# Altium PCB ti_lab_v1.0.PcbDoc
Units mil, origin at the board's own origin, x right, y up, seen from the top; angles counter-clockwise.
Board outline 7140.03 x 8380.03 mil, 2 copper layers (Top Layer, Bottom Layer); 143 components, 45 nets, 464 pads, 229 vias.
Unrouted connection lines stored in the file: 7.
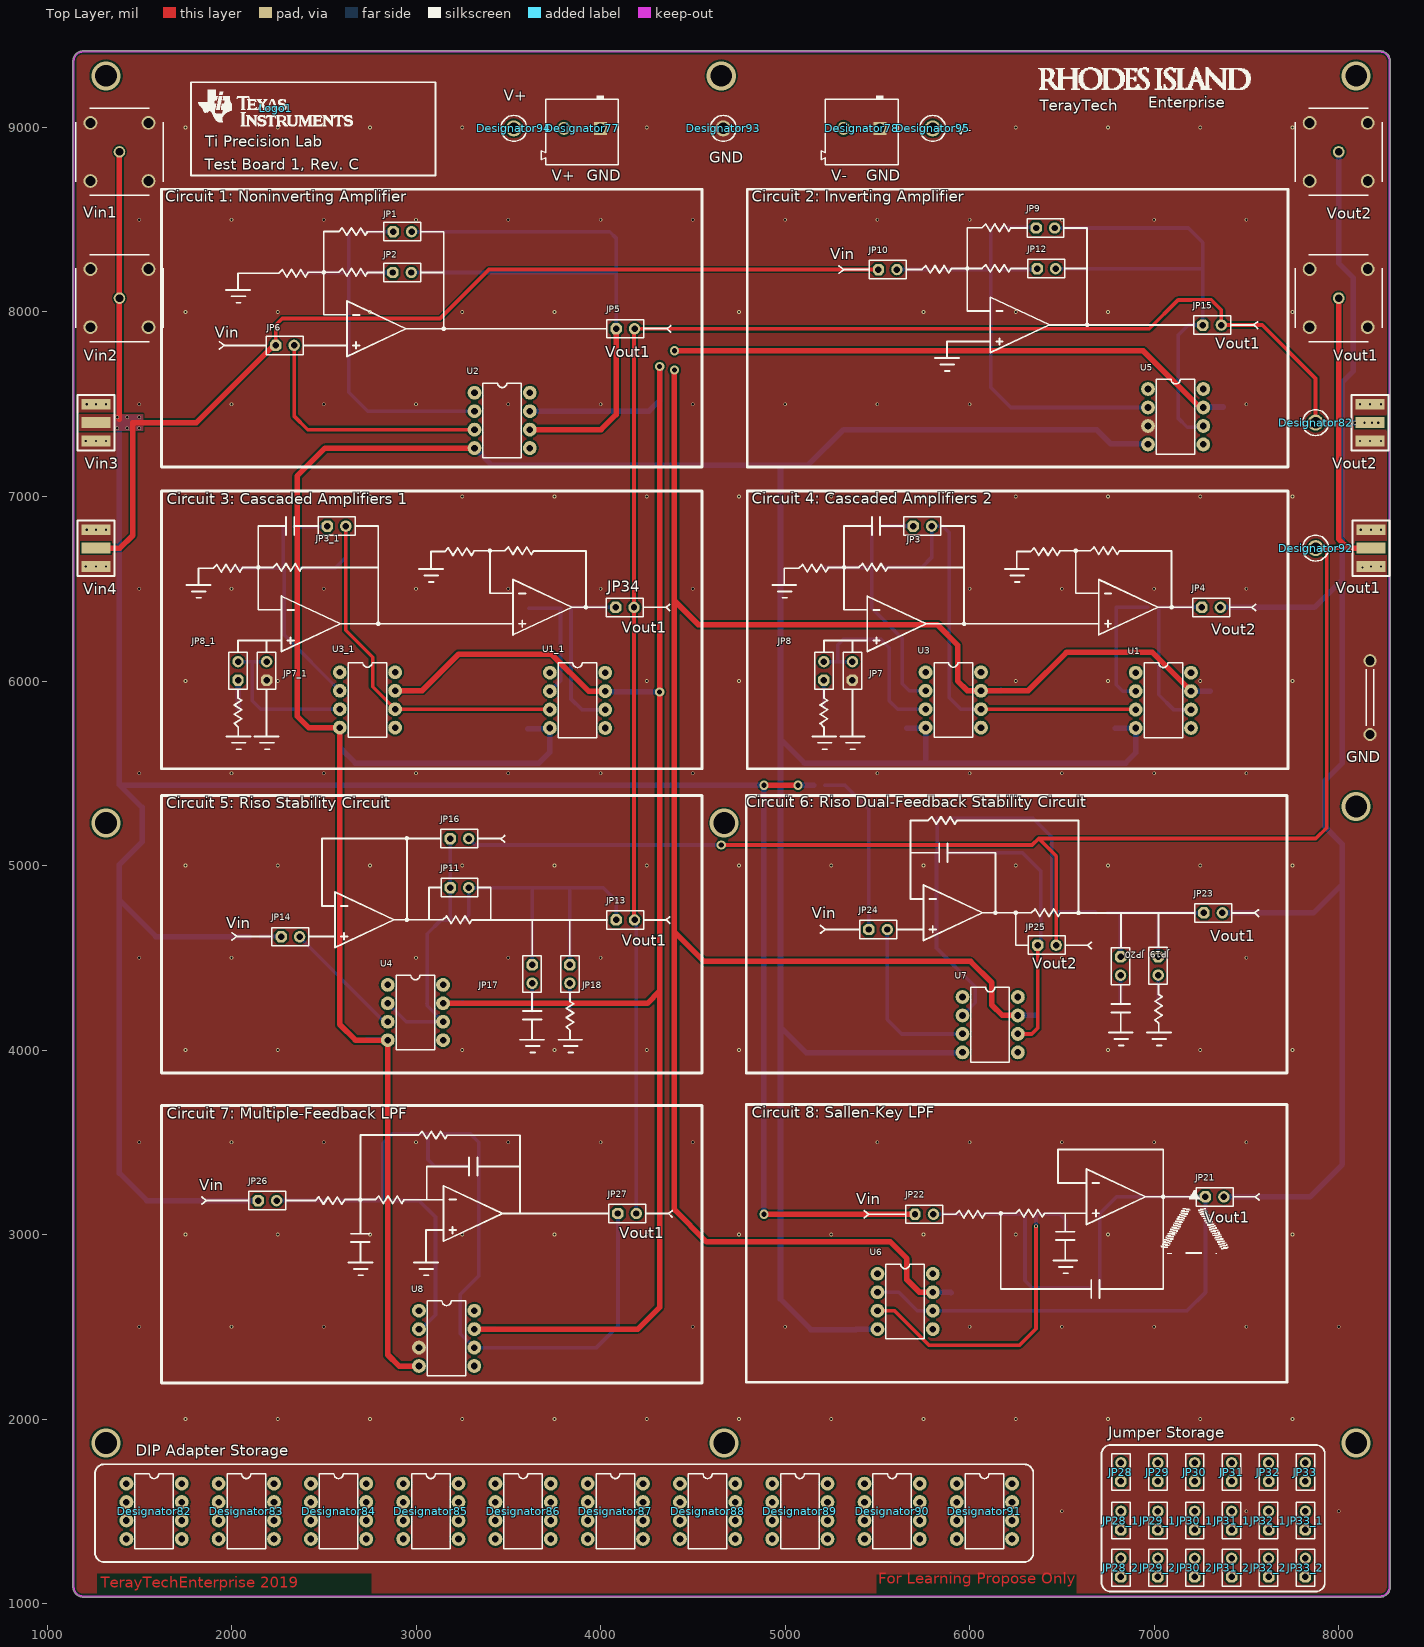
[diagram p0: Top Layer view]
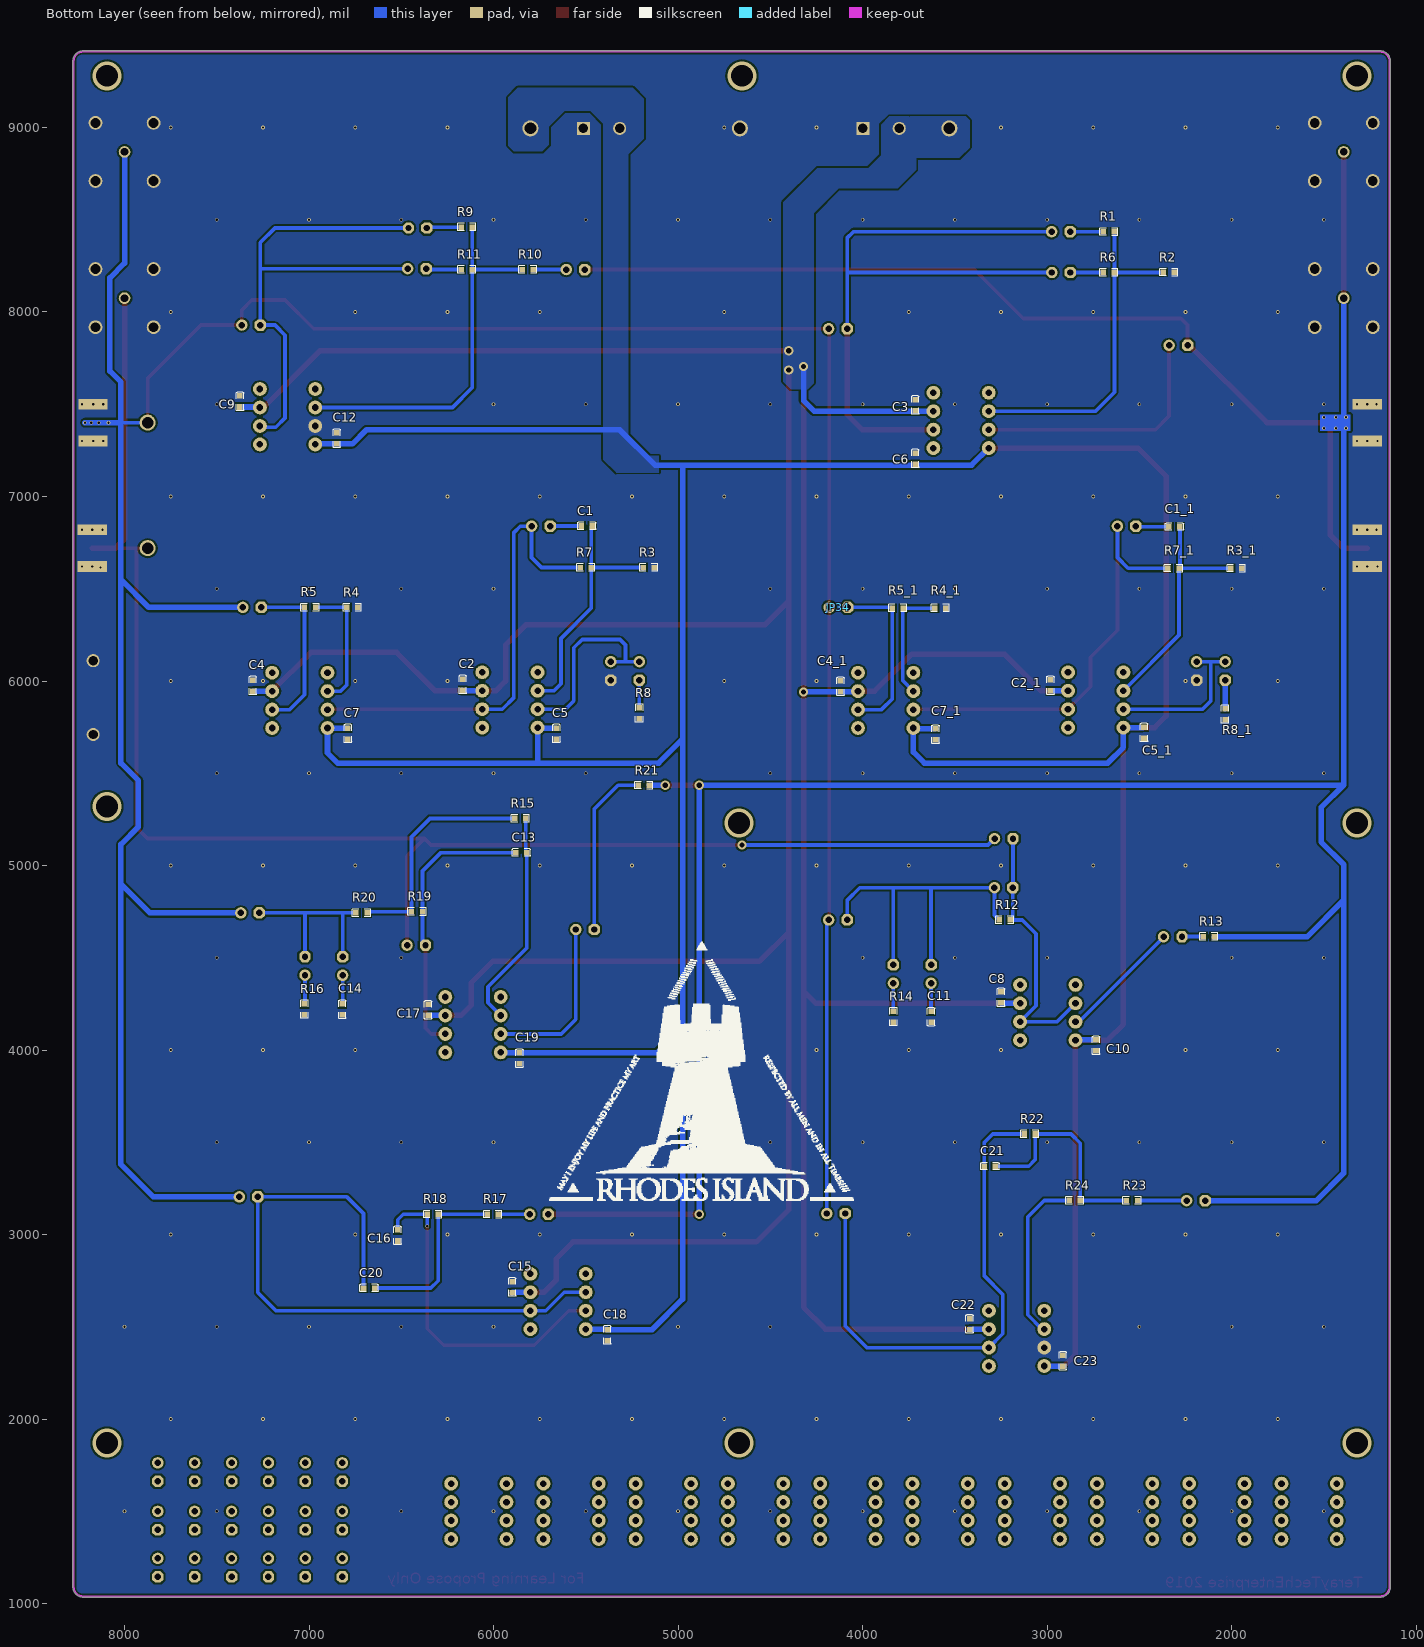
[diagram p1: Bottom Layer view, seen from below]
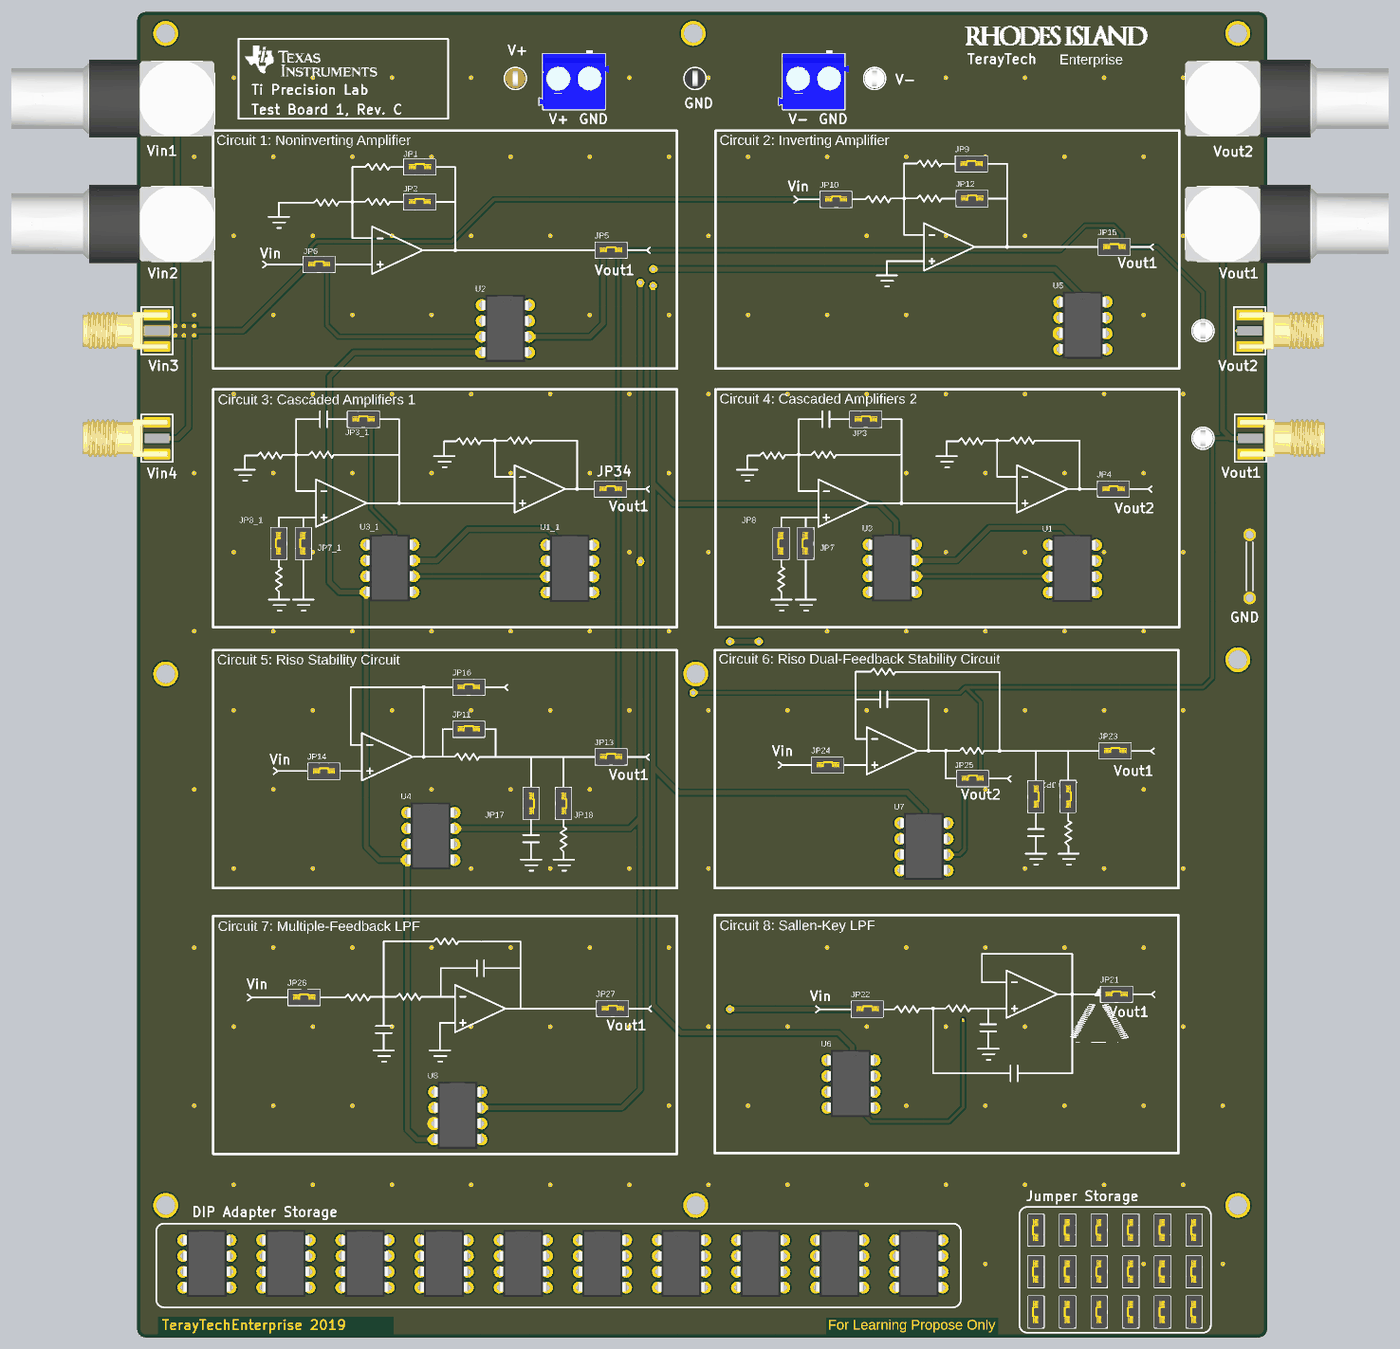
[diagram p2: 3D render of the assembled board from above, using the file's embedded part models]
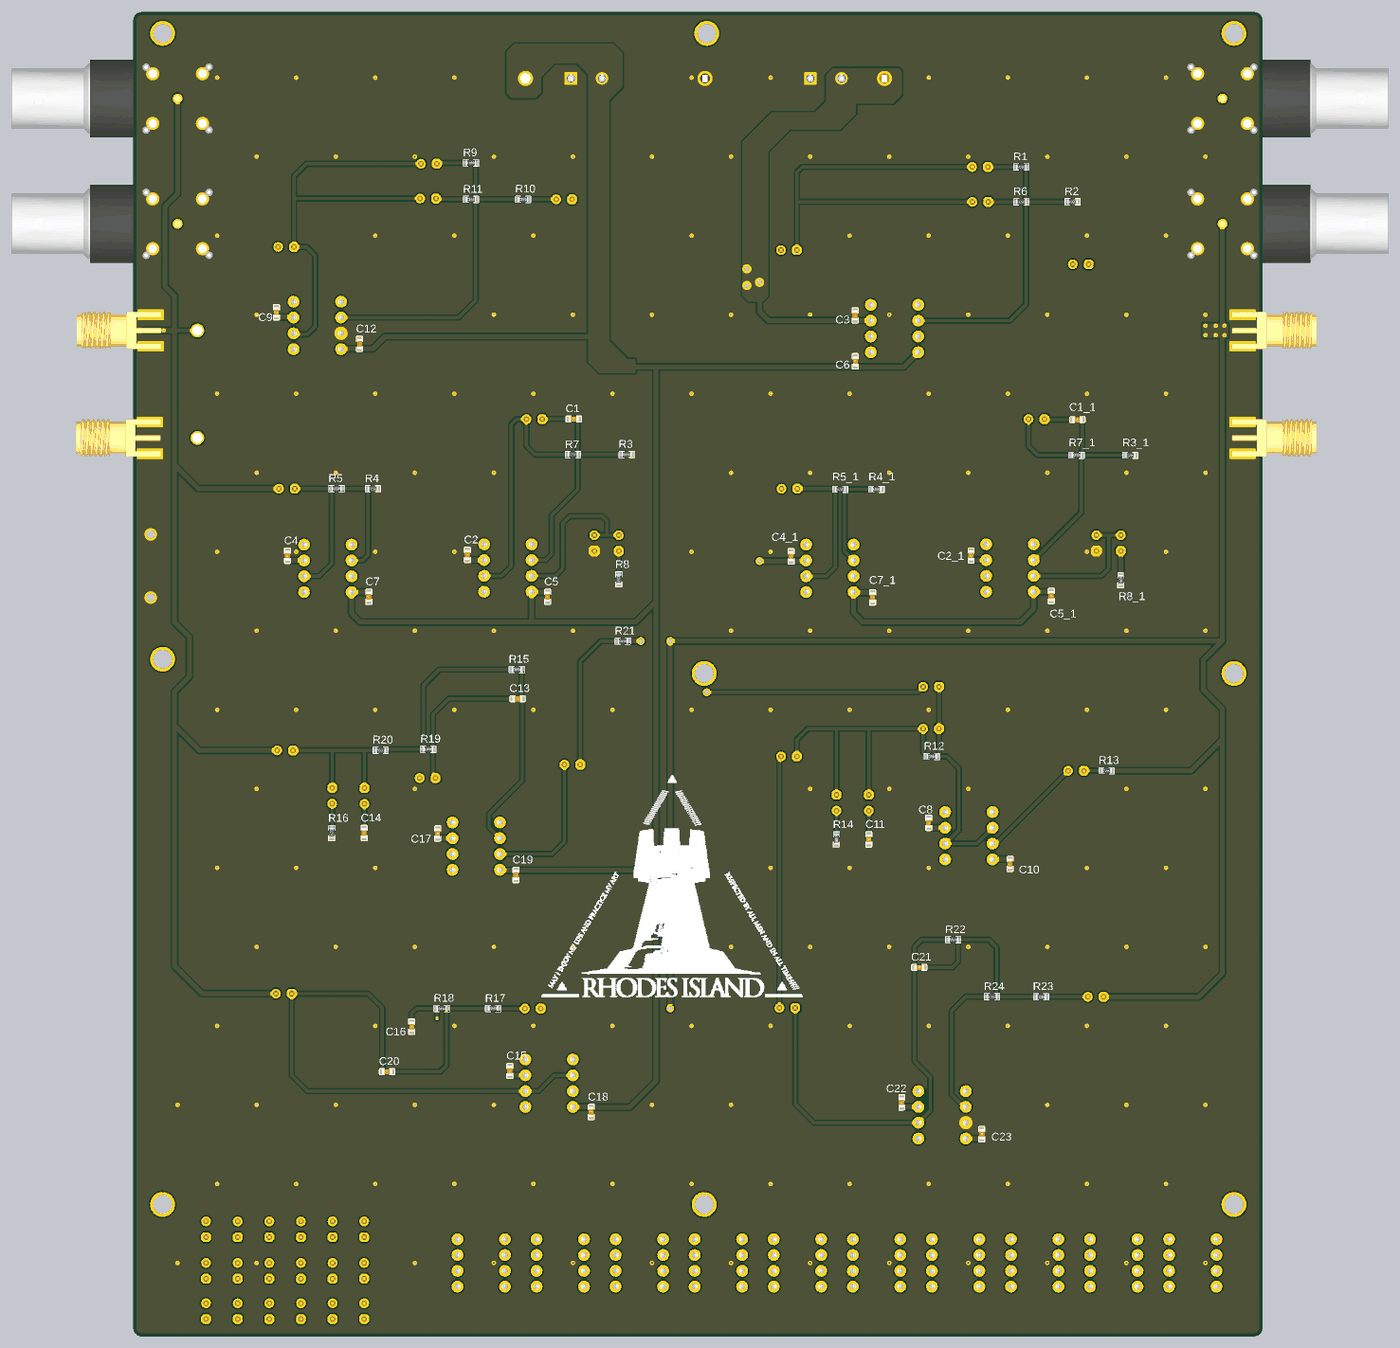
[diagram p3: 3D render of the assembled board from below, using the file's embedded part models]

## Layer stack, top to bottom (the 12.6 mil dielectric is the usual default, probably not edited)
Top Solder: solder mask 0.4, Solder Resist, Dk 3.5
Top Layer: signal copper 1.4
Dielectric 1: dielectric 12.6, FR-4, Dk 4.8
Bottom Layer: signal copper 1.4
Bottom Solder: solder mask 0.4, Solder Resist, Dk 3.5

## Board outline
1139.98,1090 ccw(c1195,1090) 1195,1034.98 8225,1034.98 ccw(c8225,1090) 8280.01,1090 8280.01,9360 ccw(c8225,9360) 8225,9415.01 1195,9415.01 ccw(c1195,9360) 1139.98,9360

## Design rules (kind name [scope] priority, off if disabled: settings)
Clearance [All] p1: gap=10 ignorepadtopadclearanceinfootprint=FALSE except(0: Arc-Hole Track-Hole SMDPad-Hole THPad-Hole Via-Hole Fill-Hole Poly-Hole Region-Hole Text-Hole)
PolygonConnect [All] p1: connectstyle=Direct reliefconductorwidth=10 reliefentries=4 polygonreliefangle="90 Angle" airgapwidth=10
RoutingVias [All] p1: holewidth=28 width=50 viastyle="Through Hole" minholewidth=28 minwidth=50 maxholewidth=28 maxwidth=50
SolderMaskExpansion [All] p1: expansion=4
Width [All] p1: maxlimit=30 minlimit=10 preferedwidth=20 minimp=50.000000 maximp=50.000000 favimp=50.000000
30 further rules are at their usual default settings.

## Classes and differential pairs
component class ti_lab: C1 C2 C3 C4 C5 C6 C7 C8 C9 C10 C11 C12 C13 C14 C15 C16 C17 C18 C19 C20 C21 C22 C23 JP1 JP2 JP3 JP4 JP5 JP6 JP7 JP8 JP9 JP10 JP11 JP12 JP13 JP14 JP15 JP16 JP17 JP18 JP19 JP20 JP21 JP22 JP23 JP24 JP25 JP26 JP27 Logo1 R1 R2 R3 R4 R5 R6 R7 R8 R9 R10 R11 R12 R13 R14 R15 R16 R17 R18 R19 R20 R21 R22 R23 R24 U1 U2 U3 U4 U5 U6 U7 U8 Vin4 Vout1 Vout2

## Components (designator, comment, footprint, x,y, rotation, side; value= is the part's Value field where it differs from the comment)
C1 "0.01uF" 0603_C 5495,6840 r0 bottom value=104
C1_1 "0.01uF" 0603_C 2310,6836 r0 bottom value=104
C2 "1uF" 0603_C 6167.28,5980 r90 bottom value=104
C2_1 "1uF" 0603_C 2982.28,5976 r90 bottom value=104
C3 "1uF" 0603_C 3715,7495 r90 bottom value=104
C4 "1uF" 0603_C 7305,5975 r90 bottom value=104
C4_1 "1uF" 0603_C 4120,5971 r90 bottom value=104
C5 "1uF" 0603_C 5660,5715 r90 bottom value=104
C5_1 "1uF" 0603_C 2475,5720 r90 bottom value=104
C6 "1uF" 0603_C 3715,7205 r270 bottom value=104
C7 "1uF" 0603_C 6790,5715 r90 bottom value=104
C7_1 "1uF" 0603_C 3605,5711 r90 bottom value=104
C8 "1uF" 0603_C 3250,4285 r90 bottom value=104
C9 "1uF" 0603_C 7375,7515 r90 bottom value=104
C10 "1uF" 0603_C 2735,4025 r90 bottom value=104
C11 "1uF" 0603_C 3629,4180 r90 bottom value=104
C12 "1uF" 0603_C 6850,7315 r270 bottom value=104
C13 "1uF" 0603_C 5850,5070 r0 bottom value=104
C14 "1uF" 0603_C 6820,4220 r90 bottom value=104
C15 "1uF" 0603_C 5899,2715 r90 bottom value=104
C16 "1uF" 0603_C 6520,2995 r270 bottom value=104
C17 "1uF" 0603_C 6355,4217.28 r90 bottom value=104
C18 "1uF" 0603_C 5384,2455 r90 bottom value=104
C19 "1uF" 0603_C 5860,3955 r90 bottom value=104
C20 "0.01uF" 0603_C 6675,2710 r0 bottom value=104
C21 "10nF" 0603_C 3310,3370 r0 bottom value=104
C22 "1uF" 0603_C 3420,2515 r90 bottom value=104
C23 "1uF" 0603_C 2915,2315 r270 bottom value=104
Designator77 "Comment" Wurth_691101710002 3900,8995 r180 top
Designator78 "Comment" Wurth_691101710002 5415,8995 r180 top
Designator82 "Comment" Keystone5007 7875,7400 r270 top
Designator82 "Comment" DIP-8 1583.54,1522.72 r270 top
Designator83 "Comment" DIP-8 2083.54,1522.72 r270 top
Designator84 "Comment" DIP-8 2583.54,1522.72 r270 top
Designator85 "Comment" DIP-8 3083.54,1522.72 r270 top
Designator86 "Comment" DIP-8 3583.54,1522.72 r270 top
Designator87 "Comment" DIP-8 4083.54,1522.72 r270 top
Designator88 "Comment" DIP-8 4583.54,1522.72 r270 top
Designator89 "Comment" DIP-8 5083.54,1522.72 r270 top
Designator90 "Comment" DIP-8 5583.54,1522.72 r270 top
Designator91 "Comment" DIP-8 6083.54,1522.72 r270 top
Designator92 "Comment" Keystone5007 7875,6720 r270 top
Designator93 "Comment" Keystone5006 4665,8995 r270 top
Designator94 "Comment" Keystone5005 3530,8995 r270 top
Designator95 "Comment" Keystone5007 5800,8995 r270 top
GND "Comment" Harwin_D3082-05 8170,5910 r90 top
JP1 "jumper" jumper#1 2875.51,8435 r0 top
JP2 "jumper" jumper#1 2874,8214 r0 top
JP3 "jumper" jumper#1 5694,6839 r0 top
JP3_1 "jumper" jumper#1 2519,6839 r0 top
JP4 "jumper" jumper#1 7259,6399 r0 top
JP5 "jumper" jumper#1 4084,7909 r0 top
JP6 "jumper" jumper#1 2239,7819 r0 top
JP7 "jumper" jumper#1 5365,6005 r90 top
JP7_1 "jumper" jumper#1 2190,6005 r90 top
JP8 "jumper" jumper#1 5210,6005 r90 top
JP8_1 "jumper" jumper#1 2035,6005 r90 top
JP9 "jumper" jumper#1 6361,8455 r0 top
JP10 "jumper" jumper#1 5506,8230 r0 top
JP11 "jumper" jumper#1 3185.46,4880 r0 top
JP12 "jumper" jumper#1 6366,8235 r0 top
JP13 "jumper" jumper#1 4084,4705 r0 top
JP14 "jumper" jumper#1 2269,4614 r0 top
JP15 "jumper" jumper#1 7264,7929 r0 top
JP16 "jumper" jumper#1 3185,5146 r0 top
JP17 "jumper" jumper#1 3629,4462 r270 top
JP18 "jumper" jumper#1 3833.12,4462 r270 top
JP19 "jumper" jumper#1 6818,4505.12 r270 top
JP20 "jumper" jumper#1 7022.12,4506.12 r270 top
JP21 "jumper" jumper#1 7278,3204 r0 top
JP22 "jumper" jumper#1 5704,3110 r0 top
JP23 "jumper" jumper#1 7270,4743.24 r0 top
JP24 "jumper" jumper#1 5454,4653.12 r0 top
JP25 "jumper" jumper#1 6369,4568.12 r0 top
JP26 "jumper" jumper#1 2144,3184 r0 top
JP27 "jumper" jumper#1 4094,3114 r0 top
JP28 "jumper" jumper#1 6820,1663 r90 top (schematic designator JP21)
JP28_1 "jumper" jumper#1 6820,1400 r90 top (schematic designator JP21)
JP28_2 "jumper" jumper#1 6820,1145 r90 top (schematic designator JP21)
JP29 "jumper" jumper#1 7020,1663 r90 top (schematic designator JP21)
JP29_1 "jumper" jumper#1 7020,1400 r90 top (schematic designator JP21)
JP29_2 "jumper" jumper#1 7020,1145 r90 top (schematic designator JP21)
JP30 "jumper" jumper#1 7220,1663 r90 top (schematic designator JP21)
JP30_1 "jumper" jumper#1 7220,1400 r90 top (schematic designator JP21)
JP30_2 "jumper" jumper#1 7220,1145 r90 top (schematic designator JP21)
JP31 "jumper" jumper#1 7420,1663 r90 top (schematic designator JP21)
JP31_1 "jumper" jumper#1 7420,1400 r90 top (schematic designator JP21)
JP31_2 "jumper" jumper#1 7420,1145 r90 top (schematic designator JP21)
JP32 "jumper" jumper#1 7620,1663 r90 top (schematic designator JP21)
JP32_1 "jumper" jumper#1 7620,1400 r90 top (schematic designator JP21)
JP32_2 "jumper" jumper#1 7620,1145 r90 top (schematic designator JP21)
JP33 "jumper" jumper#1 7820,1663 r90 top (schematic designator JP21)
JP33_1 "jumper" jumper#1 7820,1400 r90 top (schematic designator JP21)
JP33_2 "jumper" jumper#1 7820,1145 r90 top (schematic designator JP21)
JP34 "jumper" jumper#2 4081.05,6399 r0 bottom (schematic designator JP4)
Logo1 "Texas Instruments" TI_Stacked_Overlay_Small 2239,9105 r0 top
R1 "10K" 0603_R 2665,8435 r0 bottom value=1K
R2 "1K" 0603_R 2340,8215 r0 bottom
R3 "1K" 0603_R 5160,6615 r0 bottom
R3_1 "1K" 0603_R 1975,6611 r0 bottom
R4 "1K" 0603_R 6765,6399 r0 bottom
R4_1 "1K" 0603_R 3580,6395 r0 bottom
R5 "20K" 0603_R 6995,6399 r0 bottom value=1K
R5_1 "20K" 0603_R 3810,6395 r0 bottom value=1K
R6 "100K" 0603_R 2665,8214 r0 bottom value=1K
R7 "100K" 0603_R 5500,6615 r0 bottom value=1K
R7_1 "100K" 0603_R 2315,6611 r0 bottom value=1K
R8 "5K" 0603_R 5210,5825 r90 bottom value=1K
R8_1 "5K" 0603_R 2035,5820 r90 bottom value=1K
R9 "10K" 0603_R 6145,8460 r0 bottom value=1K
R10 "1K" 0603_R 5815,8230 r0 bottom
R11 "100K" 0603_R 6145,8230 r0 bottom value=1K
R12 "100" 0603_R 3230,4705 r0 bottom value=1K
R13 "100" 0603_R 2125,4615 r0 bottom value=1K
R14 "100" 0603_R 3833.12,4180 r90 bottom value=1K
R15 "4.87K" 0603_R 5855,5255 r0 bottom value=1K
R16 "100" 0603_R 7025,4220 r90 bottom value=1K
R17 "4.87K" 0603_R 6005,3110 r0 bottom value=1K
R18 "14.7K" 0603_R 6330,3110 r0 bottom value=1K
R19 "100" 0603_R 6415,4750 r0 bottom value=1K
R20 "4.99" 0603_R 6715.8,4743.24 r180 bottom value=1K
R21 "100" 0603_R 5185,5435 r0 bottom value=1K
R22 "11.3K" 0603_R 3095,3545 r0 bottom value=1K
R23 "11.3K" 0603_R 2540,3184 r0 bottom value=1K
R24 "5.76K" 0603_R 2850,3185 r0 bottom value=1K
U1 "TI-OPA-8_1" DIP-8 7053.54,5917.72 r270 top
U1_1 "TI-OPA-8_1" DIP-8 3878.54,5917.72 r270 top
U2 "TI-OPA-8_1" DIP-8 3470,7435 r270 top
U3 "TI-OPA-8_1" DIP-8 5915,5920 r270 top
U3_1 "TI-OPA-8_1" DIP-8 2740,5920 r270 top
U4 "TI-OPA-8_1" DIP-8 3000,4226 r270 top
U5 "TI-OPA-8_1" DIP-8 7120,7455 r270 top
U6 "TI-OPA-8_1" DIP-8 5654,2660 r270 top
U7 "TI-OPA-8_1" DIP-8 6115,4160 r270 top
U8 "TI-OPA-8_1" DIP-8 3169,2460 r270 top
Vin1 "Comment" BNC-8X8 1392.52,8867.48 r90 top
Vin2 "Comment" BNC-8X8 1392.52,8075 r90 top
Vin3 "SMA-KHD" SMA-2 1265,7400 r270 top (schematic designator IN1)
Vin4 "SMA-KHD" SMA-2 1265,6720 r270 top
Vout1 "Comment" BNC-8X8 8000,8075 r270 top
Vout1 "SMA-KHD" SMA-2 8175,6720 r90 top (schematic designator OUT1)
Vout2 "Comment" BNC-8X8 8000,8867.48 r270 top
Vout2 "SMA-KHD" SMA-2 8170,7400 r90 top (schematic designator OUT2)

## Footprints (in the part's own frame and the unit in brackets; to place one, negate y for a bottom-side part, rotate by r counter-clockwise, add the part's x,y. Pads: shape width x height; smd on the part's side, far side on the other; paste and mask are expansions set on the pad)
0603_C [mil] "Capacitor"
  rect 30x30 smd: 1(-30,0) 2(30,0)
  silkscreen extent -50,-20 50,20, body extent -51,-18 52,21, height 35
0603_R [mil]
  rect 30x30 smd: 1(-30,0) 2(30,0)
  silkscreen extent -49,-20 49,21, body extent -32,-16 31,16, height 18
BNC-8X8 [mm]
  round 1.6 hole 1.05: 1(0,0)
  round 1.9 hole 1.35: MH(-4,-4) MH(-4,4) MH(4,-4) MH(4,4)
  silkscreen extent -6,-6 6,6, body extent -6.25,-6 6.25,26.6, height 15.25
DIP-8 [mil]
  round 75 hole 36: 1(-127.28,-153.54) 2(-27.28,-153.54) 3(72.72,-153.54) 4(172.72,-153.54) 5(172.72,146.46) 6(72.72,146.46) 7(-27.28,146.46) 8(-127.28,146.46)
  silkscreen extent -180,-108 225,101, body extent -193,-158 233,148, height 177
Harwin_D3082-05 [mm] "Shorting Plug, 10.16mm spacing, TH"
  round 1.8 hole 1.3: 1(-5.08,0) 2(5.08,0)
  silkscreen extent -3.9,-0.53 3.9,0.53, body extent -5.6,-0.52 5.61,0.52, height 6.63
jumper#1 [mil]
  round 1 on Mech3: 0(51,1)
  oct 62x62 hole 35: 1(0,0)
  round 62 hole 35: 2(100,0)
  silkscreen extent -50,-50 150,50, body extent -50,-50 151,51, height 398
jumper#2 [mil]
  round 1 on Mech3: 0(51,-1)
  oct 62x62 hole 35: 1(0,0)
  round 62 hole 35: 2(100,0)
  body extent -50,-51 151,50, height 398
Keystone5005 [mil] "Keystone Compact loops"
  round 87 hole 63: 1(0,0)
  silkscreen extent -70,-70 70,70, body extent -63,-63 62,63, height 225
Keystone5006 [mil] "Keystone Compact loops"
  round 87 hole 63: 1(0,0)
  silkscreen extent -70,-70 70,70, body extent -63,-63 62,63, height 225
Keystone5007 [mil] "Keystone Compact loops"
  round 87 hole 63: 1(0,0)
  silkscreen extent -70,-70 70,70, body extent -63,-63 62,63, height 225
SMA-2 [mm]
  rect 1.5x4 all layers, no hole: 1(-2.54,0) 1(2.54,0)
  rect 1.5x4 smd: 2(0,0)
  silkscreen extent -3.81,-2.54 3.81,2.54, body extent -3,-11.89 3,1.71, height 3.2
TI_Stacked_Overlay_Small [mil]
  silkscreen extent -418,-98 418,98
Wurth_691101710002 [mm] "Terminal Block, 5 mm, 2x1, TH"
  rect 1.8x1.8 hole 1.3: 1(-2.5,0)
  round 1.8 hole 1.3: 2(2.5,0)
  silkscreen extent -5,-4.5 5.6,5, body extent -5.6,-4 5.6,5, height 12.5

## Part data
C1 C1_1 C2 C2_1 C3 C4 C4_1 C5 C5_1 C6 C7 C7_1 C8 C9 C10 C11 C12 C13 C14 C15 C16 C17 C18 C19 C20 C21 C22 C23: library part CAP, "Capacitor"
JP1 JP2 JP3 JP3_1 JP4 JP5 JP6 JP7 JP7_1 JP8 JP8_1 JP9 JP10 JP11 JP12 JP13 JP14 JP15 JP16 JP17 JP18 JP19 JP20 JP21 JP22 JP23 JP24 JP25 JP26 JP27 JP28 JP28_1 JP28_2 JP29 JP29_1 JP29_2 JP30 JP30_1 JP30_2 JP31 JP31_1 JP31_2 JP32 JP32_1 JP32_2 JP33 JP33_1 JP33_2 JP34: "t跳线帽"
Logo1: library part TI_Logo, "Texas Instrument Corporate Signature"
R1 R2 R3 R3_1 R4 R4_1 R5 R5_1 R6 R7 R7_1 R8 R8_1 R9 R10 R11 R12 R13 R14 R15 R16 R17 R18 R19 R20 R21 R22 R23 R24: library part RES, "Resistor"
Vin3 Vin4 Vout1 Vout2: library part SMA_KHD

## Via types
v1: diameter 20, hole 12, Top Layer to Bottom Layer, 212 vias
v2: diameter 157.48, hole 118.11, Top Layer to Bottom Layer, 9 vias
v3: diameter 50, hole 28, Top Layer to Bottom Layer, 8 vias

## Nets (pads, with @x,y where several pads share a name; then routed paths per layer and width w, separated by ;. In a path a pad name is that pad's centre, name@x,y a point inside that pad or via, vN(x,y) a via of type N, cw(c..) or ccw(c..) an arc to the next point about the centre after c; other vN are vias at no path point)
GND: C2.2 C2_1.2 C3.2 C4.2 C4_1.2 C5.1 C5_1.1 C6.1 C7.1 C7_1.1 C8.2 C9.2 C10.1 C11.1 C12.1 C14.1 C15.2 C16.2 C17.2 C18.1 C19.1 C22.2 C23.1 Designator77.1 Designator78.1 Designator93.1 GND.1 GND.2 JP7.1 JP7_1.1 R2.1 R3.1 R3_1.1 R4.1 R4_1.1 R8.1 R8_1.1 R14.1 R16.1 U5.3 U8.3 Vin1.MH Vin2.MH Vin3.1 Vin4.1 Vout1.1@8175,6620 Vout1.1@8175,6820 Vout1.MH Vout2.1@8170,7300 Vout2.1@8170,7500 Vout2.MH
  other v1: 1500,1500 2000,1500 2500,1500 3000,1500 3500,1500 4000,1500 4500,1500 5000,1500 5500,1500 6000,1500 6500,1500 7500,1500 8000,1500 1750,2000 2250,2000 2750,2000 3250,2000 3750,2000 4250,2000 4750,2000 5250,2000 5750,2000 6250,2000 6750,2000 7250,2000 7750,2000 1500,2500 2000,2500 2500,2500 4500,2500 5000,2500 6000,2500 6500,2500 7000,2500 7500,2500 8000,2500 1750,3000 2250,3000 2750,3000 3250,3000 3750,3000 4250,3000 4750,3000 5250,3000 5750,3000 6250,3000 6750,3000 7750,3000 1500,3500 2000,3500 2500,3500 3000,3500 3500,3500 4000,3500 4500,3500 5500,3500 6000,3500 6500,3500 7000,3500 7500,3500 1750,4000 2250,4000 3250,4000 3750,4000 4250,4000 4750,4000 6750,4000 7250,4000 7750,4000 1500,4500 2000,4500 3000,4500 3500,4500 4000,4500 6500,4500 7500,4500 1750,5000 2250,5000 2750,5000 3250,5000 3750,5000 4250,5000 4750,5000 5250,5000 5750,5000 6250,5000 6750,5000 7250,5000 7750,5000 1500,5500 2000,5500 2500,5500 3000,5500 3500,5500 4000,5500 4500,5500 5500,5500 6000,5500 6500,5500 7000,5500 7500,5500 1750,6000 2250,6000 4250,6000 4750,6000 6250,6000 6750,6000 7250,6000 7750,6000 1500,6500 2000,6500 2500,6500 3000,6500 3500,6500 4000,6500 4500,6500 6000,6500 6500,6500 7000,6500 7500,6500 8130,6615 1210,6620 1265,6620 1320,6620 8175,6620 8230,6620 1215,6820 1265,6820 1320,6820 8120,6820 8175,6820 8230,6820 1750,7000 2250,7000 2750,7000 3250,7000 3750,7000 4250,7000 4750,7000 5250,7000 5750,7000 6250,7000 6750,7000 7250,7000 7750,7000 1210,7300 1265,7300 1320,7300 8115,7300 8170,7300 8230,7300 1215,7500 1265,7500 1320,7500 1500,7500 2000,7500 2500,7500 3000,7500 3500,7500 4000,7500 4500,7500 5000,7500 5500,7500 6000,7500 7500,7500 8115,7500 8170,7500 8230,7500 1750,8000 2250,8000 2750,8000 3250,8000 3750,8000 4750,8000 5750,8000 6250,8000 6750,8000 7750,8000 1500,8500 2000,8500 2500,8500 3000,8500 3500,8500 4000,8500 4500,8500 5000,8500 5500,8500 6000,8500 6500,8500 7000,8500 7500,8500 1750,9000 2250,9000 2750,9000 3250,9000 4250,9000 4750,9000 6250,9000 6750,9000 7250,9000 7750,9000
NetC1_1: C1.1 C1_1.1 R3.2 R3_1.2 R7.1 R7_1.1 U3.2 U3_1.2 | length 2645.2
  Bottom Layer w20: R3_1.2 R7_1.1 ; C1_1.1 2280,6616 R7_1.1 ; U3_1.2 2285,6248.74 R7_1.1 ; R3.2@5190,6610 5195,6615 R7.1 ; C1.1 5470,6835 R7.1 ; U3.2 5672.72,5947.28 5635,5985 5635,6230 5470,6395 R7.1
NetC1_2: C1.2 C1_1.2 JP3.1 JP3_1.1 | length 349.7
  Bottom Layer w20: C1_1.2 2516,6836 JP3_1.1 ; C1.2 5693,6840 JP3.1
NetC11_2: C11.2 JP17.2 | length 152
  Bottom Layer w20: C11.2 JP17.2
NetC13_1: C13.1 R15.1 U7.2 | length 1185.2
  Bottom Layer w20: R15.1 5825,5075 C13.1 5820,4553.28 6030,4343.28 6030,4255.83 U7.2
NetC13_2: C13.2 JP25.1 R19.1 U7.6 | length 1524.7
  Top Layer w20: U7.6 6337.28,4087.28 6369,4119 JP25.1
  Bottom Layer w20: C13.2 6285,5070 6385,4970 R19.1 6385,4584.12 JP25.1
NetC14_2: C14.2 JP19.2 | length 155.9
  Bottom Layer w20: JP19.2 6818,4252 C14.2
NetC16_1: C16.1 R18.2 U6.3 | length 1821.8
  Top Layer w20: U6.3 5592.72,2587.28 5780,2400 6270,2400 6360,2490 v1(6360,3045)
  Bottom Layer w20: v1(6360,3045) R18.2 6490,3110 6520,3080 C16.1
NetC20_1: C20.1 R17.2 R18.1 | length 986.6
  Bottom Layer w20: R17.2 R18.1 6300,2750 6340,2710 C20.1
NetC20_2: C20.2 JP21.1 U6.2 U6.6 | length 3391.8
  Bottom Layer w20: U6.2 5616.72,2687.28 5716.72,2587.28 U6.6 7178.74,2587.28 7278,2686.54 JP21.1 6795,3204 6705,3114 C20.2
NetC21_1: C21.1 R22.1 R23.2 R24.1 | length 1184.2
  Bottom Layer w20: R23.2 R24.1@2809,3184 ; R24.1 2820,3495 2870,3545 R22.1 3065,3405 3100,3370 C21.1
NetC21_2: C21.2 JP27.1 R22.2 U8.6 | length 2855.9
  Bottom Layer w20: R22.2 3295,3545 3340,3500 C21.2 3340,2775 3240,2675 3240,2462.74 U8.6 3977.28,2387.28 4094,2504 JP27.1
NetIN1_2: JP6.1 JP10.1 JP22.1 JP26.1 R13.1 R21.1 Vin1.1 Vin2.1 Vin3.2 Vin4.2 | length 20079.7
  Top Layer w20: JP6.1@2239,7830 2239,7929 2275,7965 3130,7965 3395,8230 JP10.1
  Top Layer w30: Vin4.2 1395,6720 1465,6790 1465,7400 1809,7400 JP6.1@2239,7830 ; 1392.52,7417.48 Vin2.1 Vin1.1 ; v3(4885,3110) JP22.1 ; v3(4885,5435) v3(5070,5435)
  Bottom Layer w30: Vin2.1@1400,8070 1392.52,8062.52 1392.52,7370 1392.52,5440 ; R13.1 1590,4615 1392.52,4812.48 ; JP26.1 1541,3184 1392.52,3332.48 1392.52,4812.48 ; v3(4885,3110) v3(4885,5435) 1397.52,5435 1392.52,5440 ; v3(5070,5435) R21.1 ; 1392.52,4812.48 1392.52,5005.27 1515,5127.75 1515,5315 1392.52,5437.48 1392.52,5440
  other v1: 1380,7370 1435,7370 1500,7370 1380,7430 1435,7430 1500,7430
NetJP1_1: JP1.1 R1.2 | length 180.5
  Bottom Layer w20: R1.2 JP1.1
NetJP1_2: JP1.2 JP2.2 JP5.1 U2.6 | length 3692.2
  Top Layer w30: U2.6 4002.28,7362.28 4084,7444 JP5.1
  Bottom Layer w20: JP2.2 4081,8214 4084,8211 ; JP1.2 4050,8435 4084,8401 4084,8211 ; JP5.1 4084,8211
NetJP2_1: JP2.1 R6.2 | length 179
  Bottom Layer w20: R6.2 JP2.1
NetJP3_2: JP3.2 JP3_1.2 R7.2 R7_1.2 U1.3 U1_1.3 U3.6 U3_1.6 | length 4908.4
  Top Layer w20: JP3_1.2 2619,6275.24 2765,6129.24 2765,5968.74 U3_1.6 3722.72,5847.28 U1_1.3 ; U3.6 6897.72,5847.28 U1.3
  Bottom Layer w20: R7_1.2 2561,6611 2619,6669 JP3_1.2 ; R7.2 5740,6615 5794,6669 JP3.2 5856,6839 5890,6805 5890,5910 5952.72,5847.28 U3.6
NetJP4_1: JP4.1 JP34.1 R5.2 R5_1.2 U1.6 U1_1.6 | length 1860.3
  Bottom Layer w20: U1_1.6 3897.28,5845 3840,5902.28 R5_1.2 3844,6399 JP34.1 ; U1.6 7105,5845 7025,5925 R5.2 JP4.1
NetJP4_2: Designator82.1@7875,7400 JP4.2 JP5.2 JP13.2 JP15.2 JP21.2 JP23.2 JP27.2 JP34.2 Vout2.1@8000,8867.48 Vout2.2 | length 17139.3
  Top Layer w20: JP13.2@4181.05,4705 JP34.2 4181.05,7909 JP5.2 6974,7909 7130,8065 7310,8065 7364,8011 JP15.2 7586,7929 7875,7640 Designator82.1@7875,7400
  Bottom Layer w20: JP27.2 JP13.2@4194,4695 ; Designator82.1@7875,7400 8020,7400 8027.5,7400
  Bottom Layer w30: JP13.2 JP13.2@4194,4695 ; JP4.2 7869,6399 8020,6550 ; JP23.2 7863.24,4743.24 8020,4900 ; JP21.2 7844,3204 8020,3380 8020,4900 ; Vout2.1@8000,8867.48 8000,8265 8080,8185 8080,7680 8020,7620 8020,7400 8020,6550 ; 8027.5,7400 v1(8087.5,7400) v1(8140,7400) v1(8180,7400) v1(8215,7400) ; 8020,4900 8020,5115 7925,5210 7925,5460 8020,5555 8020,6550
NetJP6_2: JP6.2 U2.3 | length 1391
  Top Layer w20: JP6.2 2339,7436 2412.72,7362.28 U2.3
NetJP7_2: JP7.2 JP7_1.2 JP8.2 JP8_1.2 U3.3 U3_1.3 | length 1919.1
  Bottom Layer w20: JP8_1.2 2112.5,6105 ; JP7_1.2 2112.5,6105 ; U3_1.3 2157.72,5847.28 2112.5,5892.5 2112.5,6105 ; JP8.2 5285,6105 ; JP7.2 5285,6105 ; U3.3 5610,5847.28 5565,5892.28 5565,6180 5520,6225 5315,6225 5285,6195 5285,6105
NetJP8_1: JP8.1 JP8_1.1 R8.2 R8_1.2 | length 305
  Bottom Layer w20: R8.2 JP8.1
  Bottom Layer w30: R8_1.2 JP8_1.1
NetJP9_1: JP9.1 R9.2 | length 188.1
  Bottom Layer w20: R9.2 6356,8460 JP9.1
NetJP9_2: JP9.2 JP12.2 JP15.1 U5.6 | length 2849.2
  Bottom Layer w20: JP9.2 7185,8455 7264,8376 7264,8235 ; JP12.2 7264,8235 ; U5.6 7267.72,7382.28 7260.43,7375 7180,7375 7130,7425 7130,7874 7185,7929 JP15.1 7264,8235
NetJP10_2: JP10.2 R10.1 | length 179
  Bottom Layer w20: JP10.2 R10.1
NetJP11_1: JP11.1 JP16.1 R12.1 U4.2 U4.6 | length 1474.7
  Bottom Layer w20: U4.2 2946.46,4153.28 U4.6 3060,4239.74 3060,4255 ; 3058.28,4253.28 3060,4255 ; JP16.1 3185,4880.46 JP11.1 3185.46,4719.54 R12.1 3135,4705 3060,4630 3060,4255
NetJP11_2: JP11.2 JP13.1 JP17.1 JP18.1 R12.2 | length 1956
  Bottom Layer w20: R12.2 3285.46,4730.46 JP11.2 3629,4880 ; JP17.1 3629,4880 ; JP18.1 3833.12,4876.88 3830,4880 ; JP13.1 4084,4811 4015,4880 3830,4880 ; 3629,4880 3830,4880
NetJP12_1: JP12.1 R11.2 | length 193.1
  Bottom Layer w20: R11.2 6361,8230 JP12.1
NetJP14_1: JP14.1 R13.2 | length 114.4
  Bottom Layer w20: R13.2 2268,4615 JP14.1
NetJP14_2: JP14.2 U4.3 | length 670
  Bottom Layer w20: JP14.2 2369,4611 2826.72,4153.28 U4.3
NetJP16_2: Designator92.1 JP16.2 JP25.2 Vout1.1@8000,8075 Vout1.2 | length 8511.6
  Top Layer w20: v3(4654,5110.7) 6338.7,5110.7 6374,5146 ; JP25.2 6469,5051 6374,5146 ; Designator92.1 7935,6720 ; 8050,6720 7935,6720 ; 6374,5146 7876,5146 7935,5205 7935,6720
  Top Layer w30: Vout1.1@8000,8075 8000,6770 8050,6720 Vout1.2
  Bottom Layer w20: JP16.2 3320.3,5110.7 v3(4654,5110.7)
NetJP18_2: JP18.2 R14.2 | length 152
  Bottom Layer w20: R14.2 JP18.2
NetJP19_1: JP19.1 JP20.1 JP23.1 R20.1 | length 1001.5
  Bottom Layer w20: R20.1 6820,4743.24 ; JP19.1 6818,4741.24 6820,4743.24 ; JP20.1 7022.12,4740.35 7025,4743.24 ; JP23.1 7025,4743.24 ; 6820,4743.24 7025,4743.24
NetJP20_2: JP20.2 R16.2 | length 157.3
  Bottom Layer w20: JP20.2 7022.12,4252.88 R16.2
NetJP22_2: JP22.2 R17.1 | length 172.7
  Bottom Layer w20: JP22.2 5971,3110 R17.1@5975,3114
NetJP24_1: JP24.1 R21.2 | length 948
  Bottom Layer w20: R21.2 5325,5435 5454,5306 JP24.1 JP24.1@5452.12,4655
NetJP24_2: JP24.2 U7.3 | length 927.2
  Bottom Layer w20: JP24.2 5554,4166 5632.72,4087.28 U7.3
NetJP26_2: JP26.2 R23.1 | length 267.7
  Bottom Layer w20: JP26.2 2506,3184 R23.1@2510,3180
NetR1_1: R1.1 R2.2 R6.1 U2.2 | length 1861.7
  Bottom Layer w20: R2.2@2369,8210 2373,8214 R6.1 ; R1.1 R6.1 ; U2.2 2737.72,7462.28 2635,7565 R6.1
NetR4_2: R4.2 R4_1.2 R5.1 R5_1.1 U1.2 U1_1.2 | length 1353.4
  Bottom Layer w20: R4_1.2 R5_1.1 3782.5,6392.5 3782.5,6002.5 U1_1.2 ; U1.2 6830,5945 6795,5980 R4.2 R5.1
NetR9_1: R9.1 R10.2 R11.1 U5.2 | length 2033.1
  Bottom Layer w20: R10.2 6110,8230 6115,8235 R9.1 ; R11.1 6115,7590 6222.72,7482.28 U5.2
NetR15_2: R15.2 R19.2 R20.2 | length 1250
  Bottom Layer w20: R15.2 6345,5255 6445,5155 R19.2 6679.04,4750 R20.2
NetR24_2: R24.2 U8.2 | length 914
  Bottom Layer w20: R24.2 3015,3185 3105,3095 3105,2565 3027.28,2487.28 U8.2
V+: C2.1 C2_1.1 C3.1 C4.1 C4_1.1 C8.1 C9.1 C15.1 C17.1 C22.1 Designator77.2 Designator94.1 U1.7 U1_1.7 U2.7 U3.7 U3_1.7 U4.7 U5.7 U6.7 U7.7 U8.7 | length 25292.8
  Top Layer w30: U3_1.7 3032.28,5947.28 3230,6145 3735,6145 3935,5945 U1_1.7 ; U4.7 4253.28,4253.28 4320,4320 ; U8.7 4202.28,2487.28 4320,2605 4320,4320 ; v3(4320,7705) v3(4320,5941) 4320,4320 ; v3(4400,7685) 4400,6435 ; v3@4405,7790 6940,7790 7247.72,7482.28 U5.7 ; U6.7 5727.72,2687.28 5660,2755 5660,2870 5570,2960 4575,2960 4400,3135 4400,4640 ; U7.7 6177.72,4187.28 6120,4245 6120,4365 6005,4480 4560,4480 4400,4640 ; U1.7 6990,6155 6525,6155 6317.28,5947.28 U3.7 5987.72,5947.28 5935,6000 5935,6195 5825,6305 4530,6305 4400,6435 ; 4400,4640 4400,6435
  Bottom Layer w30: U3_1.7 2887.74,5946 C2_1.1 ; U4.7 3248.28,4253.28 C8.1 ; U8.7 C22.1@3422.72,2487.28 ; U2.7 4262.28,7462.28 4320,7520 v3(4320,7705) ; U1_1.7 4029,5941 C4_1.1 v3(4320,5941) ; U6.7 5896.72,2687.28 C15.1 ; U3.7 6167.28,5947.28 C2.1@6170,5950 ; U7.7 C17.1 ; U1.7 C4.1 ; U5.7 7269.17,7485 C9.1
  other v3: 4400,7790
V-: C5.2 C5_1.2 C6.2 C7.2 C7_1.2 C10.2 C12.2 C18.2 C19.2 C23.2 Designator78.2 Designator95.1 U1.4 U1_1.4 U2.4 U3.4 U3_1.4 U4.4 U5.4 U6.4 U7.4 U8.4 | length 20762.4
  Top Layer w30: U8.4 2907.72,2287.28 2846.46,2348.54 U4.4 2671.72,4053.28 2586.46,4138.54 U3_1.4 2417.72,5747.28 2355,5810 2355,7110 2507.28,7262.28 U2.4
  Bottom Layer w30: C5_1.2@2481.28,5747.28 U3_1.4 2586.46,5640 2671.46,5555 3665,5555 3725,5615 U1_1.4 3721,5741 C7_1.2 ; C10.2 2844.74,4055 U4.4 ; C23.2 3013.17,2285 U8.4 ; U2.4 3408.74,7170 4975,7170 ; U6.4 5386.28,2487.28 C18.2 5140,2485 4975,2650 4975,4125 ; C5.2 U3.4@5761.46,5745 ; U3.4 U3.4@5761.46,5745 ; U7.4 5959.17,3985 C19.2 5115,3985 4975,4125 ; C7.2 U1.4 6900,5610 6845,5555 5761.46,5555 ; U5.4 6963.74,7285 C12.2 6765,7285 6688.43,7361.57 5316.57,7361.57 5125,7170 4975,7170 ; 4975,4125 4975,5685 ; 4975,5685 4975,7170 ; 4975,5685 5105,5555 5761.46,5555 ; 5761.46,5555 U3.4@5761.46,5745
pads on no net: Designator82.1@1430,1650 Designator82.2 Designator82.3 Designator82.4 Designator82.5 Designator82.6 Designator82.7 Designator82.8 Designator83.1 Designator83.2 Designator83.3 Designator83.4 Designator83.5 Designator83.6 Designator83.7 Designator83.8 Designator84.1 Designator84.2 Designator84.3 Designator84.4 Designator84.5 Designator84.6 Designator84.7 Designator84.8 Designator85.1 Designator85.2 Designator85.3 Designator85.4 Designator85.5 Designator85.6 Designator85.7 Designator85.8 Designator86.1 Designator86.2 Designator86.3 Designator86.4 Designator86.5 Designator86.6 Designator86.7 Designator86.8 Designator87.1 Designator87.2 Designator87.3 Designator87.4 Designator87.5 Designator87.6 Designator87.7 Designator87.8 Designator88.1 Designator88.2 Designator88.3 Designator88.4 Designator88.5 Designator88.6 Designator88.7 Designator88.8 Designator89.1 Designator89.2 Designator89.3 Designator89.4 Designator89.5 Designator89.6 Designator89.7 Designator89.8 Designator90.1 Designator90.2 Designator90.3 Designator90.4 Designator90.5 Designator90.6 Designator90.7 Designator90.8 Designator91.1 Designator91.2 Designator91.3 Designator91.4 Designator91.5 Designator91.6 Designator91.7 Designator91.8 JP1.0 JP2.0 JP3.0 JP3_1.0 JP4.0 JP5.0 JP6.0 JP7.0 JP7_1.0 JP8.0 JP8_1.0 JP9.0 JP10.0 JP11.0 JP12.0 JP13.0 JP14.0 JP15.0 JP16.0 JP17.0 JP18.0 JP19.0 JP20.0 JP21.0 JP22.0 JP23.0 JP24.0 JP25.0 JP26.0 JP27.0 JP28.0 JP28.1 JP28.2 JP28_1.0 JP28_1.1 JP28_1.2 JP28_2.0 JP28_2.1 JP28_2.2 JP29.0 JP29.1 JP29.2 JP29_1.0 JP29_1.1 JP29_1.2 JP29_2.0 JP29_2.1 JP29_2.2 JP30.0 JP30.1 JP30.2 JP30_1.0 JP30_1.1 JP30_1.2 JP30_2.0 JP30_2.1 JP30_2.2 JP31.0 JP31.1 JP31.2 JP31_1.0 JP31_1.1 JP31_1.2 JP31_2.0 JP31_2.1 JP31_2.2 JP32.0 JP32.1 JP32.2 JP32_1.0 JP32_1.1 JP32_1.2 JP32_2.0 JP32_2.1 JP32_2.2 JP33.0 JP33.1 JP33.2 JP33_1.0 JP33_1.1 JP33_1.2 JP33_2.0 JP33_2.1 JP33_2.2 JP34.0 U1.1 U1.5 U1.8 U1_1.1 U1_1.5 U1_1.8 U2.1 U2.5 U2.8 U3.1 U3.5 U3.8 U3_1.1 U3_1.5 U3_1.8 U4.1 U4.5 U4.8 U5.1 U5.5 U5.8 U6.1 U6.5 U6.8 U7.1 U7.5 U7.8 U8.1 U8.5 U8.8
copper on no net:
  other v2: 1320,1870 4670,1870 8095,1870 1320,5230 4670,5230 8095,5320 1320,9280 4654,9280 8095,9280

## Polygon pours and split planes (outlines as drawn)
GND on Top Layer (solid, remove dead copper, pour order 8): 1040,9420 1040,935 1210,765 1240,795 8165,795 8440,1070 8385,1125 8385,9465
no net on Top Layer (solid, pour order 14): 2800,6390 2790,6380 2790,5590 3880,5590 3885,5595 3830,5650 3830,6355
NetIN1_2 on Top Layer "Top Layer-NetIN1_2" (solid, pour order 0): 1175,7445 1520,7445 1520,7355 1175,7355
GND on Bottom Layer (solid, remove dead copper, pour order 6): 1160,9545 860,9245 860,945 1125,680 8235,680 8610,1055 8490,1175 8490,9485
V- on Bottom Layer (solid, pour order 12): 5400,9015 5475,9090 5615,9090 5700,9005 5700,8905 5735,8870 5890,8870 5920,8900 5920,9165 5870,9215 5245,9215 5185,9155 5185,8982.5
V+ on Bottom Layer (solid, pour order 10): 3750,9060 3440,9060 3420,9040 3420,8890 3475,8835 3740,8835
V- on Bottom Layer (solid, pour order 4): 5235,9065 5370,9065 5405,9030 5405,7200 5335,7130 5105,7130 5105,7220 5175,7220 5270,7315 5270,8855 5185,8940 5185,9025
V+ on Bottom Layer (solid, pour order 2): 3750,9060 3710,9020 3710,8770 3810,8670 4130,8670 4265,8535 4265,7615 4297.72,7582.28 4390,7582.28 4430,7622.28 4430,8595 4245,8780 3970,8780 3900,8850 3900,9015 3855,9060

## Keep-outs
Keep-Out Layer:
  lines w10: 8275,9195 8275,9360 ccw(c8225,9360) 8225,9410 1195,9410 ccw(c1195,9360) 1145,9360 1145,9235 1145,1090 ccw(c1195,1090) 1195,1040 8225,1040 ccw(c8225,1090) 8275,1090 8275,9235

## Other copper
Top Layer:
  text "TerayTechEnterprise 2019" at 1290,1085 h60
  text "For Learning Propose Only" at 5505,1085 h100
Bottom Layer:
  rectangle net NetIN1_2: 1355,7355 1520,7445

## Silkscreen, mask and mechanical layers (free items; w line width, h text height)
Top Overlay:
  drawing of 1396 lines, arcs and shapes, not listed
  text "V+" at 3475,9145 h60
  text "TerayTech" at 6380,9090 h60
  text "Enterprise" at 6968,9085 h100
  text "V-" at 5925,8960 h60
  text "Ti Precision Lab" at 1856.96,8895 h60
  text "GND" at 4590,8810 h60
  text "Test Board 1, Rev. C" at 1855.87,8770 h60
  text "V+" at 3735,8710 h60
  text "GND" at 3925,8710 h60
  text "V-" at 5250,8710 h60
  text "GND" at 5440,8710 h60
  text "Circuit 1: Noninverting Amplifier" at 1640,8575 h100
  text "Circuit 2: Inverting Amplifier" at 4820,8575 h100
  text "Vin" at 5245,8285 h60
  text "Vin" at 1910,7861 h60
  text "Vout1" at 7330,7800 h60
  text "Vout1" at 4025,7755 h60
  text "Circuit 4: Cascaded Amplifiers 2" at 4820,6940 h100
  text "Circuit 3: Cascaded Amplifiers 1" at 1650,6935 h100
  text "Vout1" at 4115,6262.5 h60
  text "Vout2" at 7310,6250 h60
  text "Circuit 6: Riso Dual-Feedback Stability Circuit" at 4790,5295 h100
  text "Circuit 5: Riso Stability Circuit" at 1645,5290 h100
  text "Vin" at 5145,4715.12 h60
  text "Vin" at 1970,4661 h60
  text "Vout1" at 7305,4590 h60
  text "Vout1" at 4115,4565 h60
  text "Vout2" at 6340,4440 h60
  text "Circuit 8: Sallen-Key LPF" at 4820,3610 h100
  text "Circuit 7: Multiple-Feedback LPF" at 1650,3605 h100
  text "Vin" at 1825,3241 h60
  text "Vin" at 5385,3165 h60
  text "Vout1" at 7275,3065 h60
  text "Vout1" at 4100,2980 h60
  text "Jumper Storage" at 6750,1900 h60
  text "DIP Adapter Storage" at 1480,1800 h60
Bottom Overlay:
  drawing of 1776 lines, arcs and shapes, not listed
Top Solder:
  text "TerayTechEnterprise 2019" at 1290,1085 h60
  text "For Learning Propose Only" at 5505,1085 h100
